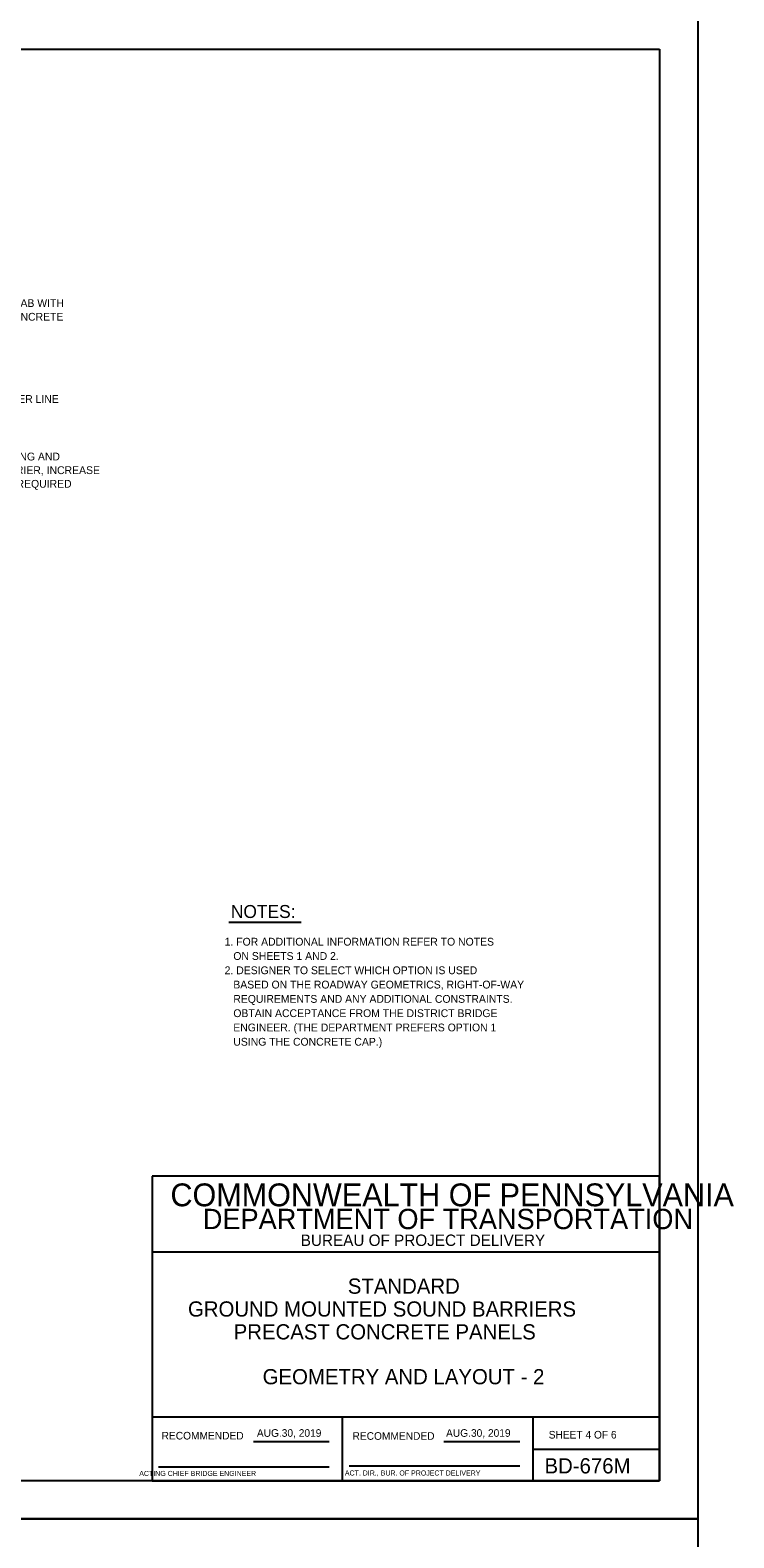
# Model space of a CAD drawing. Extents: x 3761 to 5458, y -616 to 1166.
# Drawn here: x 5180 to 5458, y -30 to 564 of the extents above; entities that cross this region are included whole.
import ezdxf

# ---------------------------------------------------------------- set-up
doc = ezdxf.new("R2010")
doc.units = 0
for name, color, linetype in [('1', 7, 'Continuous'), ('2', 7, 'Continuous'), ('PLT-BNDY', 7, 'Continuous')]:
    doc.layers.add(name, color=color, linetype=linetype)

msp = doc.modelspace()

# ---------------------------------------------------------------- linework, layer by layer
at = {"layer": '1'}
msp.add_line((5258.55, 212.78), (5287.12, 212.78), dxfattribs=at)
at = {"layer": '2'}
for p, q in [((4642.34, 556.69), (5428.34, 556.69)), ((5428.34, 556.69), (5428.34, -7.31)), ((5428.34, 112.69), (5228.34, 112.69)), ((5228.34, 112.69), (5228.34, -7.31)), ((5428.34, -7.31), (5428.34, 112.69)), ((5428.34, 82.69), (5228.34, 82.69)), ((5428.34, 17.69), (5228.34, 17.69)), ((5303.34, -7.31), (5303.34, 17.69)), ((5378.34, 17.69), (5378.34, -7.31)), ((5268.31, 8.19), (5298.07, 8.19)), ((5343.31, 8.19), (5373.21, 8.19)), ((5378.34, 5.19), (5428.34, 5.19)), ((5230.84, -1.81), (5298.07, -1.81)), ((5305.97, -1.43), (5373.21, -1.43)), ((5428.34, -7.31), (4642.34, -7.31)), ((5228.34, -7.31), (5428.34, -7.31))]:
    msp.add_line(p, q, dxfattribs=at)
at = {"layer": 'PLT-BNDY'}
for points in [[(4602.34, 571.69), (5443.34, 571.69), (5443.34, -22.31), (4602.34, -22.31)], [(4602.34, -22.31), (5443.34, -22.31), (5443.34, -616.31), (4602.34, -616.31)]]:
    msp.add_lwpolyline(points, close=True, dxfattribs=at)

# ---------------------------------------------------------------- texts
at = {"layer": '1'}
for s, height, p in [('MOMENT SLAB WITH', 3.0721, (5152.08, 455.12)), ('TYPICAL CONCRETE', 3.0721, (5152.08, 449.74)), ('GUTTER LINE', 3.0721, (5164.44, 417.35)), ('CONCRETE BARRIER, INCREASE', 3.0721, (5142.07, 389.29)), ('BETWEEN FOOTING AND', 3.0721, (5142.07, 394.67)), ('CLEARANCE AS REQUIRED', 3.0721, (5142.07, 383.92)), ('NOTES:', 5.117, (5259.39, 214.4)), ('1. FOR ADDITIONAL INFORMATION REFER TO NOTES', 3.072, (5256.94, 203.52)), ('   ON SHEETS 1 AND 2.', 3.072, (5256.94, 197.89)), ('2. DESIGNER TO SELECT WHICH OPTION IS USED', 3.072, (5256.94, 192.26)), ('   BASED ON THE ROADWAY GEOMETRICS, RIGHT-OF-WAY', 3.072, (5256.94, 186.63)), ('   OBTAIN ACCEPTANCE FROM THE DISTRICT BRIDGE', 3.072, (5256.94, 175.36)), ('   REQUIREMENTS AND ANY ADDITIONAL CONSTRAINTS.', 3.072, (5256.94, 180.99)), ('   ENGINEER. (THE DEPARTMENT PREFERS OPTION 1', 3.072, (5256.94, 169.73)), ('   USING THE CONCRETE CAP.)', 3.072, (5256.94, 164.1)), ('STANDARD', 6, (5305.48, 66.36)), ('GROUND MOUNTED SOUND BARRIERS', 6, (5242.5, 57.36)), ('PRECAST CONCRETE PANELS', 6, (5260.5, 48.36)), ('GEOMETRY AND LAYOUT - 2', 6, (5271.92, 30.69)), ('SHEET 4 OF 6', 3, (5384.63, 9.32)), ('BD-676M', 6, (5382.97, -4.43))]:
    msp.add_text(s, height=height, dxfattribs=at).set_placement(p)
at = {"layer": '2'}
for s, height, p in [('COMMONWEALTH OF PENNSYLVANIA', 9, (5235.59, 100.82)), ('DEPARTMENT OF TRANSPORTATION', 8.0002, (5248.34, 91.82)), ('BUREAU OF PROJECT DELIVERY', 4.5, (5286.93, 85.19)), ('AUG.30, 2019', 3, (5269.64, 10)), ('AUG.30, 2019', 3, (5344.19, 10)), ('       ACTING CHIEF BRIDGE ENGINEER', 2.0002, (5217.93, -5.43)), ('  ACT. DIR., BUR. OF PROJECT DELIVERY', 2.0002, (5302.78, -5.25))]:
    msp.add_text(s, height=height, dxfattribs=at).set_placement(p)
for p in [(5232.11, 8.94), (5307.33, 8.82)]:
    msp.add_text('RECOMMENDED', height=3, rotation=360, dxfattribs=at).set_placement(p)

doc.saveas('drawing.dxf')
